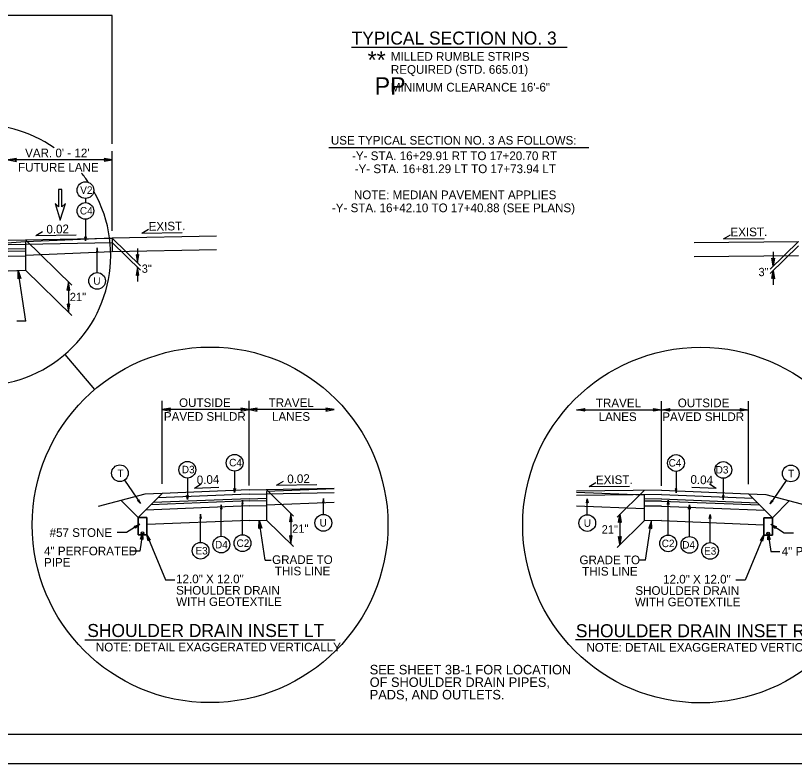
# Model space of a CAD drawing. Extents: x 1553884 to 1554215, y 810431 to 810779.
# Drawn here: x 1553971.2 to 1554061, y 810431 to 810517.2 of the extents above; entities that cross this region are included whole.
import ezdxf

# ---------------------------------------------------------------- set-up
doc = ezdxf.new("R2010")
doc.units = 0
for name, color, linetype in [('Old_Level_1', 7, 'Continuous'), ('Old_Level_15', 7, 'Continuous'), ('Old_Level_2', 7, 'Continuous'), ('Old_Level_20', 7, 'Continuous'), ('Prop Hatching', 7, 'Continuous'), ('Prop Lane Arrow CELL', 7, 'Continuous'), ('Prop Shade Light', 7, 'Continuous'), ('Typical Arrow Superelevation CELL', 7, 'Continuous'), ('Typical Detail Pavement Repair CELL', 7, 'Continuous'), ('Typical Shoulder Slope CELL', 7, 'Continuous'), ('Typical Text ID Circle CELL', 7, 'Continuous')]:
    doc.layers.add(name, color=color, linetype=linetype)

msp = doc.modelspace()

# ---------------------------------------------------------------- linework, layer by layer
at = {"layer": 'Old_Level_1'}
msp.add_line((1553976.88, 810478.089), (1553980.317, 810474.058), dxfattribs=at)
for centre in [(1553993.619, 810458.459), (1554050.156, 810458.432)]:
    msp.add_circle(centre, 20.5, dxfattribs=at)
for start, end in [(55.3594, 132.39727), (133.99022, 29.28511), (34.25429, 38.97192)]:
    msp.add_arc((1553967.115, 810489.54), 15.049, start, end, dxfattribs=at)
at = {"layer": 'Old_Level_15'}
for points in [[(1553971.295, 810500.688), (1553970.357, 810500.526), (1553971.3, 810500.36), (1553971.18, 810500.526)], [(1553981.42, 810500.365), (1553982.357, 810500.526), (1553981.415, 810500.693), (1553981.535, 810500.526)], [(1553979.336, 810491.669), (1553979.255, 810491.2), (1553979.172, 810491.672), (1553979.255, 810491.612)], [(1553980.68, 810489.933), (1553980.599, 810490.402), (1553980.516, 810489.931), (1553980.599, 810489.991)], [(1553985.095, 810489.601), (1553985.256, 810488.664), (1553985.423, 810489.606), (1553985.256, 810489.486)], [(1554058.68, 810489.214), (1554058.518, 810488.276), (1554058.352, 810489.219), (1554058.518, 810489.099)], [(1553971.492, 810486.832), (1553971.511, 810487.783), (1553971.817, 810486.876), (1553971.634, 810486.97)], [(1553985.418, 810487.226), (1553985.256, 810488.164), (1553985.09, 810487.221), (1553985.256, 810487.341)], [(1554058.357, 810486.839), (1554058.518, 810487.776), (1554058.685, 810486.834), (1554058.518, 810486.954)], [(1553977.458, 810485.53), (1553977.296, 810486.468), (1553977.13, 810485.525), (1553977.296, 810485.645)], [(1553977.135, 810483.905), (1553977.296, 810482.968), (1553977.463, 810483.91), (1553977.296, 810483.791)], [(1553989.053, 810471.904), (1553988.116, 810471.743), (1553989.058, 810471.576), (1553988.939, 810471.743)], [(1553997.178, 810471.581), (1553998.116, 810471.743), (1553997.173, 810471.909), (1553997.293, 810471.743)], [(1553999.053, 810471.904), (1553998.116, 810471.743), (1553999.058, 810471.576), (1553998.939, 810471.743)], [(1554006.977, 810471.581), (1554007.914, 810471.743), (1554006.971, 810471.909), (1554007.091, 810471.743)], [(1554036.798, 810471.554), (1554035.86, 810471.715), (1554036.803, 810471.882), (1554036.683, 810471.715)], [(1554044.721, 810471.877), (1554045.659, 810471.715), (1554044.716, 810471.549), (1554044.836, 810471.715)], [(1554046.596, 810471.554), (1554045.659, 810471.715), (1554046.601, 810471.882), (1554046.482, 810471.715)], [(1554054.721, 810471.877), (1554055.659, 810471.715), (1554054.716, 810471.549), (1554054.836, 810471.715)], [(1553996.536, 810462.636), (1553996.455, 810462.168), (1553996.372, 810462.639), (1553996.455, 810462.579)], [(1554047.238, 810462.609), (1554047.319, 810462.14), (1554047.402, 810462.612), (1554047.319, 810462.552)], [(1553991.082, 810461.834), (1553991.001, 810461.365), (1553990.918, 810461.836), (1553991.001, 810461.776)], [(1554052.692, 810461.807), (1554052.773, 810461.338), (1554052.856, 810461.809), (1554052.773, 810461.749)], [(1553985.26, 810461.247), (1553985.588, 810460.903), (1553985.395, 810461.341), (1553985.359, 810461.244)], [(1553997.439, 810460.846), (1553997.358, 810461.315), (1553997.275, 810460.844), (1553997.358, 810460.903)], [(1554006.757, 810461.01), (1554006.676, 810461.479), (1554006.593, 810461.008), (1554006.676, 810461.068)], [(1554037.018, 810460.983), (1554037.098, 810461.452), (1554037.182, 810460.981), (1554037.098, 810461.041)], [(1554046.336, 810460.819), (1554046.416, 810461.288), (1554046.5, 810460.817), (1554046.416, 810460.876)], [(1554058.515, 810461.22), (1554058.187, 810460.876), (1554058.38, 810461.314), (1554058.416, 810461.217)], [(1553994.999, 810460.311), (1553994.918, 810460.78), (1553994.835, 810460.308), (1553994.918, 810460.368)], [(1554048.776, 810460.284), (1554048.857, 810460.753), (1554048.94, 810460.281), (1554048.857, 810460.341)], [(1553992.615, 810459.225), (1553992.535, 810459.693), (1553992.451, 810459.222), (1553992.535, 810459.282)], [(1553999.251, 810458.048), (1553999.269, 810458.999), (1553999.576, 810458.092), (1553999.393, 810458.186)], [(1554003.089, 810458.828), (1554002.927, 810459.765), (1554002.761, 810458.823), (1554002.927, 810458.942)], [(1554040.686, 810458.741), (1554040.847, 810459.678), (1554041.014, 810458.736), (1554040.847, 810458.855)], [(1554051.159, 810459.198), (1554051.24, 810459.666), (1554051.323, 810459.195), (1554051.24, 810459.255)], [(1553984.885, 810458.273), (1553985.544, 810458.545), (1553985.013, 810458.063), (1553985.022, 810458.217)], [(1554044.524, 810458.021), (1554044.505, 810458.972), (1554044.199, 810458.065), (1554044.382, 810458.159)], [(1554058.761, 810458.042), (1554058.23, 810458.518), (1554058.895, 810458.248), (1554058.752, 810458.19)], [(1553985.618, 810456.802), (1553985.838, 810457.48), (1553985.861, 810456.763), (1553985.75, 810456.869)], [(1553986.497, 810456.603), (1553986.338, 810457.298), (1553986.725, 810456.694), (1553986.575, 810456.729)], [(1554002.766, 810457.203), (1554002.927, 810456.265), (1554003.094, 810457.208), (1554002.927, 810457.088)], [(1554057.054, 810456.669), (1554057.437, 810457.271), (1554057.28, 810456.571), (1554057.199, 810456.702)], [(1554057.917, 810456.74), (1554057.937, 810457.453), (1554058.161, 810456.771), (1554058.025, 810456.842)], [(1554041.009, 810457.116), (1554040.847, 810456.178), (1554040.68, 810457.121), (1554040.847, 810457.001)]]:
    msp.add_lwpolyline(points, close=True, dxfattribs=at)
at = {"layer": 'Old_Level_2'}
msp.add_line((1553906.821, 810434.329), (1554154.321, 810434.329), dxfattribs=at)
at = {"layer": 'Old_Level_20'}
for p, q in [((1553982.357, 810491.5), (1553972.357, 810491.1)), ((1553972.357, 810491.3), (1553977.675, 810486.097)), ((1553994.357, 810491.74), (1553982.357, 810491.5)), ((1553982.357, 810491.5), (1553982.357, 810489.915)), ((1553982.357, 810491.5), (1553985.593, 810488.334)), ((1553972.357, 810491.1), (1553963.311, 810490.376)), ((1553972.357, 810491.1), (1553972.357, 810489.515)), ((1553982.357, 810491), (1553985.593, 810487.834)), ((1554049.417, 810490.993), (1554061.417, 810491.113)), ((1554061.417, 810491.113), (1554058.181, 810487.947)), ((1554061.417, 810490.613), (1554058.181, 810487.447)), ((1553982.357, 810489.915), (1553972.357, 810489.515)), ((1553994.357, 810490.155), (1553982.357, 810489.915)), ((1553985.256, 810490.33), (1553985.256, 810488.664)), ((1554049.417, 810489.408), (1554061.417, 810489.528)), ((1554058.518, 810489.943), (1554058.518, 810488.276)), ((1553972.357, 810487.8), (1553977.675, 810482.597)), ((1553985.256, 810488.164), (1553985.256, 810486.497)), ((1554058.518, 810487.776), (1554058.518, 810486.11)), ((1553977.296, 810486.468), (1553977.296, 810482.968)), ((1554007.914, 810462.628), (1554000.116, 810462.316)), ((1554000.116, 810462.516), (1554003.254, 810459.446)), ((1554000.116, 810462.316), (1554000.116, 810460.731)), ((1554035.86, 810462.241), (1554043.659, 810461.929)), ((1554043.659, 810462.429), (1554040.521, 810459.359)), ((1554043.659, 810461.929), (1554043.659, 810460.344)), ((1554007.914, 810461.043), (1554000.116, 810460.731)), ((1554035.86, 810460.656), (1554043.659, 810460.344)), ((1554000.116, 810459.016), (1554003.254, 810455.946)), ((1554002.927, 810459.765), (1554002.927, 810456.265)), ((1554040.847, 810459.678), (1554040.847, 810456.178)), ((1554043.659, 810458.929), (1554040.521, 810455.859))]:
    msp.add_line(p, q, dxfattribs=at)
at = {"layer": 'Prop Hatching'}
for p, q in [((1553982.357, 810517.168), (1553967.887, 810517.168)), ((1553982.357, 810502.394), (1553982.357, 810517.168))]:
    msp.add_line(p, q, dxfattribs=at)
msp.add_lwpolyline([(1553976.951, 810495.492), (1553976.545, 810495.117), (1553976.545, 810497.117), (1553976.17, 810497.117), (1553976.17, 810495.117), (1553975.764, 810495.492), (1553976.357, 810493.585)], close=True, dxfattribs=at)
at = {"layer": 'Prop Lane Arrow CELL'}
msp.add_line((1553901.353, 810430.954), (1554156.35, 810430.954), dxfattribs=at)
at = {"layer": 'Prop Shade Light'}
for p, q in [((1553970.357, 810491.26), (1553982.357, 810491.5)), ((1553970.357, 810490.76), (1553982.357, 810491)), ((1553970.357, 810490.26), (1553972.357, 810490.3)), ((1553970.357, 810490.01), (1553972.357, 810490.05)), ((1553972.357, 810489.515), (1553972.357, 810487.8)), ((1553970.357, 810489.427), (1553972.357, 810489.467)), ((1553970.357, 810487.76), (1553972.357, 810487.8)), ((1553998.116, 810462.476), (1554007.914, 810462.672)), ((1553988.116, 810462.076), (1553985.338, 810459.298)), ((1553998.116, 810461.976), (1553987.595, 810461.555)), ((1553998.116, 810462.476), (1553988.116, 810462.076)), ((1553998.116, 810461.976), (1554007.914, 810462.172)), ((1554045.659, 810462.449), (1554035.86, 810462.351)), ((1554045.659, 810461.949), (1554035.86, 810461.851)), ((1554045.659, 810462.449), (1554055.659, 810462.049)), ((1554045.659, 810461.949), (1554056.18, 810461.528)), ((1554055.659, 810462.049), (1554058.437, 810459.271)), ((1553998.116, 810461.226), (1553986.814, 810460.774)), ((1553998.116, 810461.476), (1553987.074, 810461.034)), ((1553998.116, 810461.476), (1554000.116, 810461.516)), ((1553998.116, 810461.226), (1554000.116, 810461.266)), ((1554045.659, 810461.449), (1554043.659, 810461.429)), ((1554045.659, 810461.199), (1554043.659, 810461.179)), ((1554045.659, 810461.449), (1554056.7, 810461.007)), ((1554045.659, 810461.199), (1554056.961, 810460.747)), ((1553998.116, 810460.643), (1553986.206, 810460.166)), ((1553998.116, 810460.643), (1554000.116, 810460.683)), ((1554000.116, 810460.731), (1554000.116, 810459.016)), ((1554045.659, 810460.616), (1554043.659, 810460.596)), ((1554043.659, 810460.344), (1554043.659, 810458.929)), ((1554045.659, 810460.616), (1554057.569, 810460.139)), ((1553998.116, 810458.976), (1554000.116, 810459.016)), ((1553998.116, 810458.976), (1553986.338, 810458.505)), ((1554045.659, 810458.949), (1554043.659, 810458.929)), ((1554045.659, 810458.949), (1554057.437, 810458.478))]:
    msp.add_line(p, q, dxfattribs=at)
for points in [[(1553985.338, 810457.298), (1553986.338, 810457.298), (1553986.338, 810459.298), (1553985.338, 810459.298)], [(1553986.338, 810457.298), (1553985.338, 810457.298), (1553985.338, 810459.298), (1553986.338, 810459.298)], [(1554058.437, 810457.271), (1554057.437, 810457.271), (1554057.437, 810459.271), (1554058.437, 810459.271)], [(1554057.437, 810457.271), (1554058.437, 810457.271), (1554058.437, 810459.271), (1554057.437, 810459.271)]]:
    msp.add_lwpolyline(points, close=True, dxfattribs=at)
for centre in [(1553985.838, 810457.48), (1553985.838, 810457.48), (1554057.937, 810457.453), (1554057.937, 810457.453)]:
    msp.add_circle(centre, 0.167, dxfattribs=at)
at = {"layer": 'Typical Arrow Superelevation CELL'}
for p, q in [((1554009.92, 810513.517), (1554034.793, 810513.517)), ((1554007.295, 810501.971), (1554037.254, 810501.971)), ((1553973.525, 810491.816), (1553974.308, 810492.289)), ((1553985.76, 810492.082), (1553986.543, 810492.556)), ((1553973.525, 810491.816), (1553978.185, 810491.909)), ((1553985.76, 810492.082), (1553990.42, 810492.176)), ((1554052.809, 810491.441), (1554053.596, 810491.906)), ((1554052.809, 810491.441), (1554057.47, 810491.488)), ((1553972.4, 810481.923), (1553971.511, 810487.783)), ((1553972.4, 810481.923), (1553971.34, 810481.923)), ((1553988.116, 810463.191), (1553988.116, 810472.743)), ((1554055.659, 810463.164), (1554055.659, 810472.715)), ((1554001.283, 810463.032), (1554002.066, 810463.505)), ((1553991.835, 810462.694), (1553992.608, 810463.182)), ((1553991.835, 810462.694), (1553994.63, 810462.805)), ((1554001.283, 810463.032), (1554005.943, 810463.125)), ((1554037.3, 810462.879), (1554038.088, 810463.344)), ((1554037.3, 810462.879), (1554041.961, 810462.925)), ((1554051.94, 810462.667), (1554049.145, 810462.778)), ((1554051.94, 810462.667), (1554051.166, 810463.155)), ((1553999.968, 810454.396), (1553999.269, 810458.999)), ((1554043.806, 810454.369), (1554044.505, 810458.972)), ((1553999.968, 810454.396), (1554000.676, 810454.396)), ((1554043.806, 810454.369), (1554043.099, 810454.369)), ((1553979.182, 810445.22), (1554008.056, 810445.22)), ((1554064.592, 810445.192), (1554035.719, 810445.192))]:
    msp.add_line(p, q, dxfattribs=at)
for points in [[(1553985.544, 810458.545), (1553983.974, 810457.557), (1553982.913, 810457.557)], [(1554058.23, 810458.518), (1554059.801, 810457.53), (1554060.862, 810457.53)], [(1553985.838, 810457.48), (1553985.541, 810455.423), (1553984.481, 810455.423)], [(1553986.338, 810457.298), (1553988.497, 810452.114), (1553989.558, 810452.114)], [(1554057.437, 810457.271), (1554055.277, 810452.087), (1554054.216, 810452.087)], [(1554057.937, 810457.453), (1554058.233, 810455.396), (1554059.294, 810455.396)]]:
    msp.add_lwpolyline(points, dxfattribs=at)
at = {"layer": 'Typical Shoulder Slope CELL'}
for p, q in [((1553982.357, 810492.366), (1553982.357, 810501.526)), ((1553982.357, 810500.526), (1553970.357, 810500.526)), ((1553998.116, 810462.996), (1553998.116, 810472.743)), ((1554045.659, 810462.969), (1554045.659, 810472.715)), ((1553998.116, 810471.743), (1553988.116, 810471.743)), ((1554007.914, 810471.743), (1553998.116, 810471.743)), ((1554035.86, 810471.715), (1554045.659, 810471.715)), ((1554045.659, 810471.715), (1554055.659, 810471.715)), ((1553986.116, 810461.996), (1553980.715, 810460.578)), ((1553988.116, 810462.076), (1553986.116, 810461.996)), ((1554055.659, 810462.049), (1554057.659, 810461.969)), ((1554057.659, 810461.969), (1554063.06, 810460.551)), ((1553983.363, 810461.273), (1553985.338, 810459.298)), ((1554060.411, 810461.246), (1554058.437, 810459.271))]:
    msp.add_line(p, q, dxfattribs=at)
at = {"layer": 'Typical Text ID Circle CELL'}
for p, q in [((1553979.255, 810496.087), (1553979.255, 810495.609)), ((1553979.255, 810493.686), (1553979.255, 810491.2)), ((1553980.599, 810487.534), (1553980.599, 810490.402)), ((1553996.455, 810464.653), (1553996.455, 810462.168)), ((1554047.319, 810464.626), (1554047.319, 810462.14)), ((1553983.772, 810463.608), (1553985.588, 810460.903)), ((1553991.001, 810463.85), (1553991.001, 810461.365)), ((1554052.773, 810463.823), (1554052.773, 810461.338)), ((1554060.002, 810463.581), (1554058.187, 810460.876)), ((1553997.358, 810457.307), (1553997.358, 810461.315)), ((1554006.676, 810459.651), (1554006.676, 810461.479)), ((1554037.098, 810459.624), (1554037.098, 810461.452)), ((1554046.416, 810457.28), (1554046.416, 810461.288)), ((1553994.918, 810457.14), (1553994.918, 810460.78)), ((1554048.857, 810457.113), (1554048.857, 810460.753)), ((1553992.535, 810456.435), (1553992.535, 810459.693)), ((1554051.24, 810456.408), (1554051.24, 810459.666))]:
    msp.add_line(p, q, dxfattribs=at)
for centre in [(1553979.255, 810497.048), (1553979.255, 810494.647), (1553980.6, 810486.573), (1553996.455, 810465.614), (1554047.319, 810465.587), (1553983.236, 810464.407), (1553991.001, 810464.812), (1554052.773, 810464.785), (1554060.538, 810464.38), (1554006.676, 810458.69), (1554037.098, 810458.663), (1553997.358, 810456.346), (1554046.416, 810456.319), (1553992.535, 810455.474), (1553994.918, 810456.179), (1554048.857, 810456.151), (1554051.24, 810455.447)]:
    msp.add_circle(centre, 0.962, dxfattribs=at)

# ---------------------------------------------------------------- texts
at = {"layer": 'Old_Level_20'}
for s, p in [('3"', (1553985.741, 810487.515)), ('3"', (1554056.824, 810487.128)), ('21"', (1553977.455, 810484.25)), ('21"', (1554003.086, 810457.547)), ('21"', (1554038.754, 810457.46))]:
    msp.add_text(s, height=0.9558, dxfattribs=at).set_placement(p)
at = {"layer": 'Typical Arrow Superelevation CELL'}
for s, height, p in [('TYPICAL SECTION NO. 3', 1.5, (1554009.936, 810513.825)), ('**', 2, (1554011.778, 810511.059)), ('MILLED RUMBLE STRIPS', 1, (1554014.458, 810511.956)), ('REQUIRED (STD. 665.01)', 1, (1554014.458, 810510.456)), ('PP', 2, (1554012.586, 810508.06)), ('MINIMUM CLEARANCE 16\'-6"', 1, (1554014.458, 810508.414)), ('USE TYPICAL SECTION NO. 3 AS FOLLOWS:', 1, (1554007.542, 810502.291)), ("VAR. 0' - 12'", 1, (1553972.305, 810500.827)), ('-Y- STA. 16+29.91 RT TO 17+20.70 RT', 1, (1554009.979, 810500.503)), ('FUTURE LANE', 1, (1553971.491, 810499.174)), ('-Y- STA. 16+81.29 LT TO 17+73.94 LT', 1, (1554010.29, 810499.003)), ('NOTE: MEDIAN PAVEMENT APPLIES', 1, (1554010.196, 810496.003)), ('-Y- STA. 16+42.10 TO 17+40.88 (SEE PLANS)', 1, (1554007.661, 810494.503)), ('OUTSIDE', 1, (1553990.048, 810472.043)), ('TRAVEL', 1, (1554000.374, 810472.043)), ('TRAVEL', 1, (1554038.085, 810472.016)), ('OUTSIDE', 1, (1554047.523, 810472.016)), ('PAVED SHLDR', 1, (1553988.298, 810470.45)), ('LANES', 1, (1554000.76, 810470.45)), ('LANES', 1, (1554038.403, 810470.423)), ('PAVED SHLDR', 1, (1554045.733, 810470.423)), ('#57 STONE', 1, (1553975.129, 810457.068)), ('4" PERFORATED', 1, (1553974.489, 810454.943)), ('4" PERFORATED', 1, (1554059.507, 810454.916)), ('PIPE', 1, (1553974.489, 810453.632)), ('GRADE TO ', 1, (1554000.771, 810453.944)), ('GRADE TO ', 1, (1554036.191, 810453.917)), ('THIS LINE', 1, (1554001.082, 810452.633)), ('THIS LINE', 1, (1554036.502, 810452.606)), ('12.0" X 12.0"', 1, (1553989.708, 810451.722)), ('12.0" X 12.0"', 1, (1554045.834, 810451.695)), ('SHOULDER DRAIN', 1, (1553989.708, 810450.411)), ('SHOULDER DRAIN', 1, (1554042.635, 810450.384)), ('WITH GEOTEXTILE', 1, (1553989.708, 810449.1)), ('WITH GEOTEXTILE', 1, (1554042.567, 810449.073)), ('SHOULDER DRAIN INSET LT', 1.5, (1553979.471, 810445.528)), ('SHOULDER DRAIN INSET RT', 1.5, (1554035.774, 810445.501)), ('NOTE: DETAIL EXAGGERATED VERTICALLY', 1, (1553980.459, 810443.863)), ('NOTE: DETAIL EXAGGERATED VERTICALLY', 1, (1554036.996, 810443.836)), ('SEE SHEET 3B-1 FOR LOCATION', 1.1, (1554012.023, 810441.216)), ('OF SHOULDER DRAIN PIPES,', 1.1, (1554012.023, 810439.774)), ('PADS, AND OUTLETS.', 1.1, (1554012.023, 810438.332))]:
    msp.add_text(s, height=height, dxfattribs=at).set_placement(p)
for s, rotation, p in [('0.02', 1.14587, (1553974.766, 810492.032)), ('EXIST.', 1.14587, (1553986.548, 810492.349)), ('EXIST.', 0.57294, (1554053.6, 810491.7)), ('0.04', 2.29061, (1553992.104, 810463.122)), ('0.02', 1.14587, (1554002.524, 810463.248)), ('EXIST.', 0.57294, (1554038.091, 810463.137)), ('0.04', 357.70939, (1554048.965, 810463.204))]:
    msp.add_text(s, height=1, rotation=rotation, dxfattribs=at).set_placement(p)
at = {"layer": 'Typical Detail Pavement Repair CELL'}
for s, height, p in [('V2', 0.8608, (1553978.659, 810496.615)), ('C4', 0.8608, (1553978.62, 810494.241)), ('U', 0.861, (1553980.17, 810486.142)), ('D3', 0.8608, (1553990.367, 810464.405)), ('C4', 0.8608, (1553995.82, 810465.208)), ('C4', 0.8608, (1554046.47, 810465.181)), ('T', 0.861, (1553982.953, 810463.976)), ('D3', 0.8608, (1554051.89, 810464.378)), ('T', 0.861, (1554060.247, 810463.949)), ('U', 0.861, (1554006.246, 810458.259)), ('U', 0.861, (1554036.689, 810458.232)), ('D4', 0.8608, (1553994.192, 810455.748)), ('C2', 0.8608, (1553996.672, 810455.915)), ('C2', 0.8608, (1554045.673, 810455.888)), ('D4', 0.8608, (1554048.038, 810455.721)), ('E3', 0.8608, (1553991.939, 810455.043)), ('E3', 0.8608, (1554050.552, 810455.016))]:
    msp.add_text(s, height=height, dxfattribs=at).set_placement(p)

doc.saveas('drawing.dxf')
